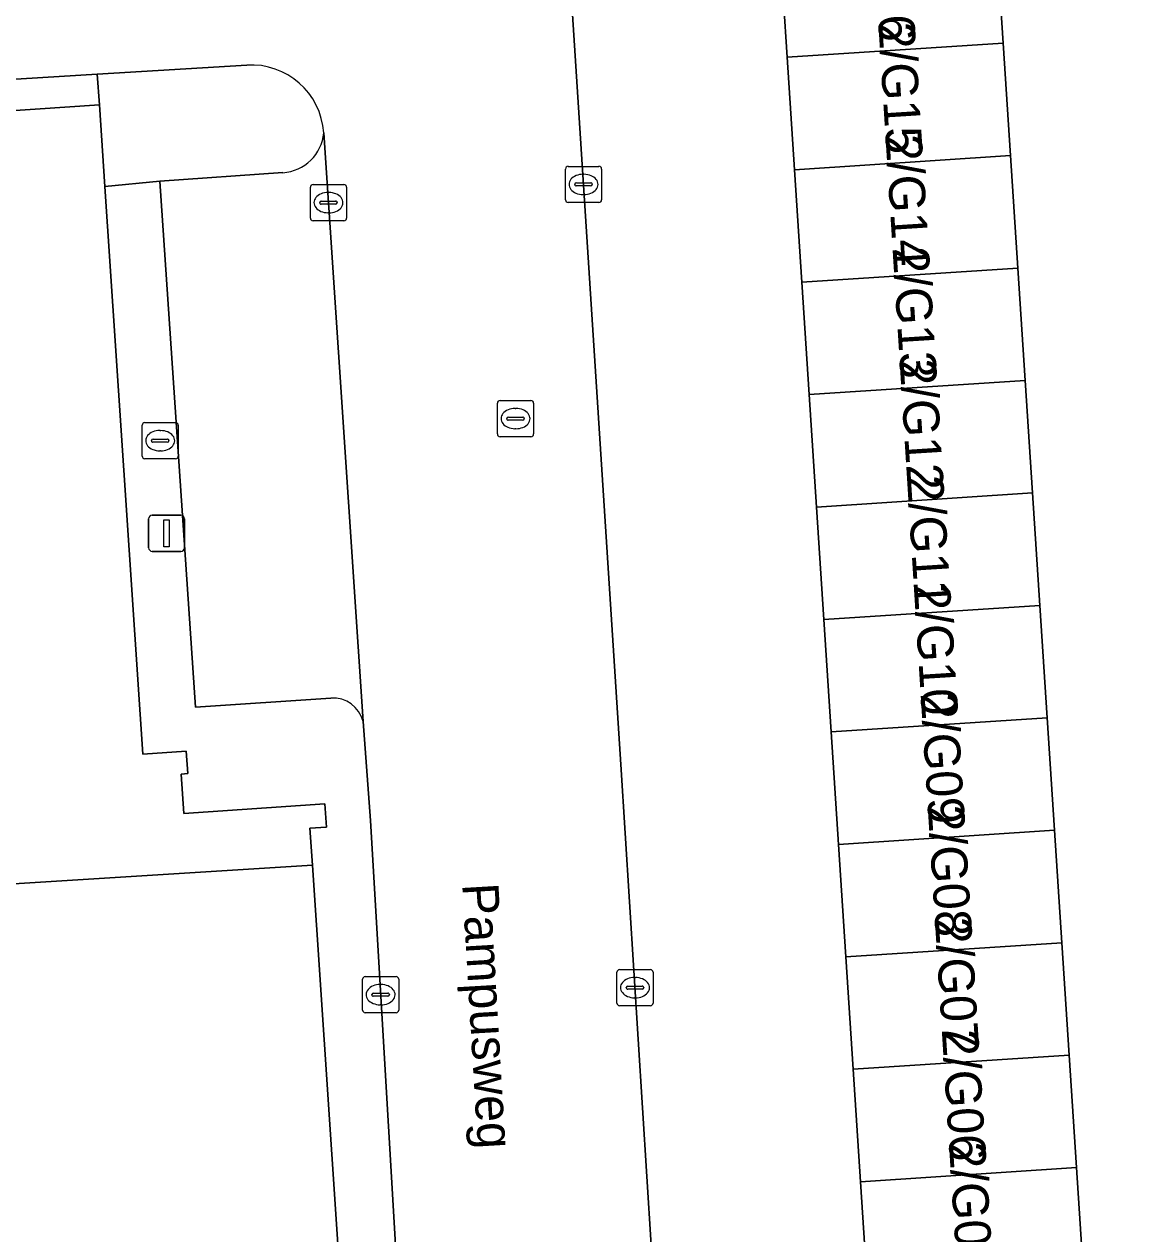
# Model space of a CAD drawing. Extents: x 159680 to 160786, y 387323 to 388340.
# Drawn here: x 160323.38 to 160353.93, y 387792.33 to 387825.78 of the extents above; entities that cross this region are included whole.
import ezdxf

# ---------------------------------------------------------------- set-up
doc = ezdxf.new("R2010")
doc.units = 0
for name, color, linetype in [('IMGEO_Kolk', 7, 'Continuous'), ('IMGEO_Lichtmast', 7, 'Continuous'), ('IMGEO_Openbare_ruimte_label', 7, 'Continuous'), ('IMGEO_Pand', 7, 'Continuous'), ('IMGEO_Pand_nummerreeks', 7, 'Continuous'), ('IMGEO_Parkeervlak_open', 7, 'Continuous'), ('IMGEO_Rijbaan_lokaal_open', 7, 'Continuous'), ('IMGEO_Rioolput', 7, 'Continuous'), ('IMGEO_Voetpad_open', 7, 'Continuous')]:
    doc.layers.add(name, color=color, linetype=linetype)

msp = doc.modelspace()

# ---------------------------------------------------------------- linework, layer by layer
at = {"layer": 'IMGEO_Kolk'}
for p, q in [((160338.348, 387820.92), (160338.348, 387821.772)), ((160338.423, 387821.846), (160339.275, 387821.846)), ((160339.349, 387821.772), (160339.349, 387820.92)), ((160331.369, 387821.342), (160332.221, 387821.342)), ((160338.607, 387821.34), (160338.607, 387821.352)), ((160338.65, 387821.389), (160339.048, 387821.389)), ((160338.836, 387821.626), (160338.861, 387821.626)), ((160339.091, 387821.352), (160339.091, 387821.34)), ((160331.294, 387820.416), (160331.294, 387821.268)), ((160331.782, 387821.122), (160331.807, 387821.122)), ((160332.295, 387821.268), (160332.295, 387820.416)), ((160339.045, 387821.303), (160338.647, 387821.303)), ((160338.859, 387821.066), (160338.834, 387821.066)), ((160331.553, 387820.836), (160331.553, 387820.848)), ((160331.991, 387820.799), (160331.593, 387820.799)), ((160331.596, 387820.885), (160331.994, 387820.885)), ((160332.037, 387820.848), (160332.037, 387820.836)), ((160339.275, 387820.846), (160338.423, 387820.846)), ((160332.221, 387820.342), (160331.369, 387820.342)), ((160331.805, 387820.562), (160331.78, 387820.562)), ((160339.846, 387799.639), (160340.698, 387799.639)), ((160332.736, 387798.519), (160332.736, 387799.371)), ((160332.811, 387799.445), (160333.663, 387799.445)), ((160333.737, 387799.371), (160333.737, 387798.519)), ((160339.771, 387798.713), (160339.771, 387799.565)), ((160340.259, 387799.419), (160340.284, 387799.419)), ((160340.772, 387799.565), (160340.772, 387798.713)), ((160332.995, 387798.939), (160332.995, 387798.951)), ((160333.433, 387798.902), (160333.035, 387798.902)), ((160333.038, 387798.988), (160333.436, 387798.988)), ((160333.224, 387799.225), (160333.249, 387799.225)), ((160333.479, 387798.951), (160333.479, 387798.939)), ((160340.03, 387799.133), (160340.03, 387799.145)), ((160340.468, 387799.096), (160340.07, 387799.096)), ((160340.073, 387799.182), (160340.471, 387799.182)), ((160340.514, 387799.145), (160340.514, 387799.133)), ((160333.247, 387798.665), (160333.222, 387798.665)), ((160340.698, 387798.639), (160339.846, 387798.639)), ((160340.282, 387798.859), (160340.257, 387798.859)), ((160333.663, 387798.445), (160332.811, 387798.445))]:
    msp.add_line(p, q, dxfattribs=at)
for points in [[(160338.348, 387820.92), (160338.348, 387821.772)], [(160338.423, 387821.846), (160339.275, 387821.846)], [(160339.349, 387821.772), (160339.349, 387820.92)], [(160331.369, 387821.342), (160332.221, 387821.342)], [(160331.294, 387820.416), (160331.294, 387821.268)], [(160332.295, 387821.268), (160332.295, 387820.416)], [(160339.275, 387820.846), (160338.423, 387820.846)], [(160332.221, 387820.342), (160331.369, 387820.342)], [(160339.846, 387799.639), (160340.698, 387799.639)], [(160332.736, 387798.519), (160332.736, 387799.371)], [(160332.811, 387799.445), (160333.663, 387799.445)], [(160333.737, 387799.371), (160333.737, 387798.519)], [(160339.771, 387798.713), (160339.771, 387799.565)], [(160340.772, 387799.565), (160340.772, 387798.713)], [(160340.698, 387798.639), (160339.846, 387798.639)], [(160333.663, 387798.445), (160332.811, 387798.445)]]:
    msp.add_lwpolyline(points, dxfattribs=at)
for centre, radius, start, end in [((160338.425, 387821.77), 0.0765, 91.552, 178.448), ((160338.425, 387821.77), 0.0765, 91.552, 178.448), ((160339.273, 387821.77), 0.0765, 1.552, 88.448), ((160339.273, 387821.77), 0.0765, 1.552, 88.448), ((160331.371, 387821.266), 0.0765, 91.552, 178.448), ((160331.371, 387821.266), 0.0765, 91.552, 178.448), ((160332.219, 387821.266), 0.0765, 1.552, 88.448), ((160332.219, 387821.266), 0.0765, 1.552, 88.448), ((160338.647, 387821.349), 0.0403, 85.8775, 175.7526), ((160338.644, 387821.339), 0.0366, 178.938, 274.7102), ((160339.048, 387821.346), 0.043, 264.8664, 352.4533), ((160339.052, 387821.351), 0.0386, 1.7309, 96.639), ((160331.593, 387820.845), 0.0403, 85.8775, 175.7526), ((160331.59, 387820.835), 0.0366, 178.938, 274.7102), ((160331.994, 387820.842), 0.043, 264.8664, 352.4533), ((160331.998, 387820.847), 0.0386, 1.7309, 96.639), ((160338.425, 387820.922), 0.0765, 181.552, 268.448), ((160338.425, 387820.922), 0.0765, 181.552, 268.448), ((160339.273, 387820.922), 0.0765, 271.552, 358.448), ((160339.273, 387820.922), 0.0765, 271.552, 358.448), ((160331.371, 387820.418), 0.0765, 181.552, 268.448), ((160331.371, 387820.418), 0.0765, 181.552, 268.448), ((160332.219, 387820.418), 0.0765, 271.552, 358.448), ((160332.219, 387820.418), 0.0765, 271.552, 358.448), ((160339.848, 387799.563), 0.0765, 91.552, 178.448), ((160339.848, 387799.563), 0.0765, 91.552, 178.448), ((160340.696, 387799.563), 0.0765, 1.552, 88.448), ((160340.696, 387799.563), 0.0765, 1.552, 88.448), ((160332.813, 387799.369), 0.0765, 91.552, 178.448), ((160332.813, 387799.369), 0.0765, 91.552, 178.448), ((160333.661, 387799.369), 0.0765, 1.552, 88.448), ((160333.661, 387799.369), 0.0765, 1.552, 88.448), ((160333.035, 387798.948), 0.0403, 85.8775, 175.7526), ((160333.032, 387798.938), 0.0366, 178.938, 274.7102), ((160333.436, 387798.945), 0.043, 264.8664, 352.4533), ((160333.44, 387798.95), 0.0386, 1.7309, 96.639), ((160340.07, 387799.142), 0.0403, 85.8775, 175.7526), ((160340.067, 387799.132), 0.0366, 178.938, 274.7102), ((160340.471, 387799.139), 0.043, 264.8664, 352.4533), ((160340.475, 387799.144), 0.0386, 1.7309, 96.639), ((160339.848, 387798.715), 0.0765, 181.552, 268.448), ((160339.848, 387798.715), 0.0765, 181.552, 268.448), ((160340.696, 387798.715), 0.0765, 271.552, 358.448), ((160340.696, 387798.715), 0.0765, 271.552, 358.448), ((160332.813, 387798.521), 0.0765, 181.552, 268.448), ((160332.813, 387798.521), 0.0765, 181.552, 268.448), ((160333.661, 387798.521), 0.0765, 271.552, 358.448), ((160333.661, 387798.521), 0.0765, 271.552, 358.448)]:
    msp.add_arc(centre, radius, start, end, dxfattribs=at)
for centre, major_axis, ratio, start_param, end_param in [((160338.835, 387821.346), (-0.387, 0.002), 0.722429, 4.712389, 7.853982), ((160338.86, 387821.346), (-0.39, 0.002), 0.717154, 1.570796, 4.712389), ((160331.781, 387820.842), (-0.387, 0.002), 0.722429, 4.712389, 7.853982), ((160331.806, 387820.842), (-0.39, 0.002), 0.717154, 1.570796, 4.712389), ((160340.258, 387799.139), (-0.387, 0.002), 0.722429, 4.712389, 7.853982), ((160340.283, 387799.139), (-0.39, 0.002), 0.717154, 1.570796, 4.712389), ((160333.223, 387798.945), (-0.387, 0.002), 0.722429, 4.712389, 7.853982), ((160333.248, 387798.945), (-0.39, 0.002), 0.717154, 1.570796, 4.712389)]:
    msp.add_ellipse(centre, major_axis=major_axis, ratio=ratio, start_param=start_param, end_param=end_param, dxfattribs=at)
at = {"layer": 'IMGEO_Lichtmast'}
for p, q in [((160326.822, 387811.302), (160326.822, 387812.102)), ((160326.822, 387812.102), (160326.822, 387811.302)), ((160326.922, 387812.202), (160327.712, 387812.202)), ((160327.712, 387812.202), (160326.922, 387812.202)), ((160327.812, 387812.102), (160327.812, 387811.302)), ((160327.812, 387811.302), (160327.812, 387812.102)), ((160327.712, 387811.202), (160326.922, 387811.202)), ((160326.922, 387811.202), (160327.712, 387811.202))]:
    msp.add_line(p, q, dxfattribs=at)
msp.add_lwpolyline([(160327.242, 387812.077), (160327.392, 387812.077), (160327.392, 387811.327), (160327.242, 387811.327), (160327.242, 387812.077)], dxfattribs=at)
for centre, start, end in [((160326.922, 387812.102), 90, 180), ((160326.922, 387812.102), 90, 180), ((160327.712, 387812.102), 0, 90), ((160327.712, 387812.102), 360, 90), ((160326.922, 387811.302), 180, 270), ((160326.922, 387811.302), 180, 270), ((160327.712, 387811.302), 270, 0), ((160327.712, 387811.302), 270, 0)]:
    msp.add_arc(centre, 0.1, start, end, dxfattribs=at)
at = {"layer": 'IMGEO_Pand'}
for points in [[(160344.482, 387824.862), (160350.454, 387825.251), (160350.251, 387828.36), (160344.279, 387827.97)], [(160344.684, 387821.753), (160350.656, 387822.142), (160350.454, 387825.251), (160344.482, 387824.862)], [(160325.609, 387821.289), (160325.458, 387823.545), (160312.863, 387822.702), (160314.285, 387801.439), (160319.097, 387801.761), (160331.352, 387802.523), (160331.283, 387803.548), (160331.738, 387803.578), (160331.695, 387804.219), (160327.791, 387803.958), (160327.719, 387805.043), (160327.902, 387805.056), (160327.861, 387805.674), (160326.659, 387805.594)], [(160344.887, 387818.644), (160350.859, 387819.034), (160350.656, 387822.142), (160344.684, 387821.753)], [(160345.09, 387815.535), (160351.062, 387815.925), (160350.859, 387819.034), (160344.887, 387818.644)], [(160345.292, 387812.427), (160351.264, 387812.816), (160351.062, 387815.925), (160345.09, 387815.535)], [(160345.495, 387809.318), (160351.467, 387809.707), (160351.264, 387812.816), (160345.292, 387812.427)], [(160345.698, 387806.209), (160351.67, 387806.598), (160351.467, 387809.707), (160345.495, 387809.318)], [(160345.9, 387803.1), (160351.872, 387803.49), (160351.67, 387806.598), (160345.698, 387806.209)], [(160346.103, 387799.991), (160352.075, 387800.381), (160351.872, 387803.49), (160345.9, 387803.1)], [(160331.352, 387802.523), (160319.097, 387801.761), (160322.017, 387758.116), (160322.036, 387757.833), (160333.839, 387758.606), (160334.288, 387758.635), (160334.155, 387760.62)], [(160346.306, 387796.883), (160352.278, 387797.272), (160352.075, 387800.381), (160346.103, 387799.991)], [(160346.509, 387793.774), (160352.481, 387794.163), (160352.278, 387797.272), (160346.306, 387796.883)], [(160346.711, 387790.665), (160352.683, 387791.054), (160352.481, 387794.163), (160346.509, 387793.774)]]:
    msp.add_lwpolyline(points, close=True, dxfattribs=at)
at = {"layer": 'IMGEO_Parkeervlak_open'}
for points in [[(160338.406, 387828.202), (160339.882, 387805.311), (160341.198, 387784.423), (160341.952, 387772.208)], [(160345.9, 387803.1), (160345.698, 387806.209), (160345.495, 387809.318), (160345.292, 387812.427), (160345.09, 387815.535), (160344.887, 387818.644), (160344.684, 387821.753), (160344.482, 387824.862), (160344.279, 387827.97), (160339.407, 387827.52)], [(160332.752, 387806.497), (160331.665, 387822.773)], [(160330.537, 387821.671), (160327.133, 387821.44), (160328.12, 387806.893), (160331.86, 387807.147)], [(160342.911, 387772.843), (160347.83, 387773.164), (160347.522, 387778.23), (160347.319, 387781.338), (160347.117, 387784.447), (160346.914, 387787.556), (160346.711, 387790.665), (160346.509, 387793.774), (160346.306, 387796.883), (160346.103, 387799.991), (160345.9, 387803.1)]]:
    msp.add_lwpolyline(points, dxfattribs=at)
for centre, radius, start, end in [((160330.455, 387822.883), 1.215, 273.863, 354.801), ((160331.918, 387806.289), 0.86, 13.9996, 93.8388)]:
    msp.add_arc(centre, radius, start, end, dxfattribs=at)
at = {"layer": 'IMGEO_Rijbaan_lokaal_open'}
for points in [[(160341.952, 387772.208), (160341.198, 387784.423), (160339.882, 387805.311), (160338.406, 387828.202), (160338.395, 387828.368)], [(160264.374, 387822.431), (160266.548, 387822.576), (160274.398, 387823.082), (160274.439, 387822.446), (160274.521, 387821.163), (160280.899, 387821.601), (160307.674, 387823.303), (160325.4, 387824.392), (160329.533, 387824.646)], [(160331.665, 387822.773), (160332.752, 387806.497), (160332.954, 387803.761), (160334.935, 387770.099)]]:
    msp.add_lwpolyline(points, dxfattribs=at)
msp.add_arc((160329.656, 387822.636), 2.013, 3.8934, 93.5068, dxfattribs=at)
at = {"layer": 'IMGEO_Rioolput'}
for p, q in [((160336.467, 387814.446), (160336.467, 387815.298)), ((160336.542, 387815.372), (160337.394, 387815.372)), ((160337.468, 387815.298), (160337.468, 387814.446)), ((160336.955, 387815.152), (160336.98, 387815.152)), ((160326.641, 387813.835), (160326.641, 387814.687)), ((160326.716, 387814.761), (160327.568, 387814.761)), ((160327.642, 387814.687), (160327.642, 387813.835)), ((160336.726, 387814.866), (160336.726, 387814.878)), ((160337.164, 387814.829), (160336.766, 387814.829)), ((160336.769, 387814.915), (160337.167, 387814.915)), ((160337.21, 387814.878), (160337.21, 387814.866)), ((160326.943, 387814.304), (160327.341, 387814.304)), ((160327.129, 387814.541), (160327.154, 387814.541)), ((160337.394, 387814.372), (160336.542, 387814.372)), ((160336.978, 387814.592), (160336.953, 387814.592)), ((160326.9, 387814.255), (160326.9, 387814.267)), ((160327.338, 387814.218), (160326.94, 387814.218)), ((160327.152, 387813.981), (160327.127, 387813.981)), ((160327.384, 387814.267), (160327.384, 387814.255)), ((160327.568, 387813.761), (160326.716, 387813.761))]:
    msp.add_line(p, q, dxfattribs=at)
for points in [[(160336.467, 387814.446), (160336.467, 387815.298)], [(160336.542, 387815.372), (160337.394, 387815.372)], [(160337.468, 387815.298), (160337.468, 387814.446)], [(160326.641, 387813.835), (160326.641, 387814.687)], [(160326.716, 387814.761), (160327.568, 387814.761)], [(160327.642, 387814.687), (160327.642, 387813.835)], [(160337.394, 387814.372), (160336.542, 387814.372)], [(160327.568, 387813.761), (160326.716, 387813.761)]]:
    msp.add_lwpolyline(points, dxfattribs=at)
for centre, radius, start, end in [((160336.544, 387815.296), 0.0765, 91.552, 178.448), ((160336.544, 387815.296), 0.0765, 91.552, 178.448), ((160337.392, 387815.296), 0.0765, 1.552, 88.448), ((160337.392, 387815.296), 0.0765, 1.552, 88.448), ((160326.718, 387814.685), 0.0765, 91.552, 178.448), ((160326.718, 387814.685), 0.0765, 91.552, 178.448), ((160327.566, 387814.685), 0.0765, 1.552, 88.448), ((160327.566, 387814.685), 0.0765, 1.552, 88.448), ((160336.766, 387814.875), 0.0403, 85.8775, 175.7526), ((160336.763, 387814.865), 0.0366, 178.938, 274.7102), ((160337.167, 387814.872), 0.043, 264.8664, 352.4533), ((160337.171, 387814.877), 0.0386, 1.7309, 96.639), ((160326.94, 387814.264), 0.0403, 85.8775, 175.7526), ((160327.345, 387814.266), 0.0386, 1.7309, 96.639), ((160336.544, 387814.448), 0.0765, 181.552, 268.448), ((160336.544, 387814.448), 0.0765, 181.552, 268.448), ((160337.392, 387814.448), 0.0765, 271.552, 358.448), ((160337.392, 387814.448), 0.0765, 271.552, 358.448), ((160326.937, 387814.254), 0.0366, 178.938, 274.7102), ((160327.341, 387814.261), 0.043, 264.8664, 352.4533), ((160326.718, 387813.837), 0.0765, 181.552, 268.448), ((160326.718, 387813.837), 0.0765, 181.552, 268.448), ((160327.566, 387813.837), 0.0765, 271.552, 358.448), ((160327.566, 387813.837), 0.0765, 271.552, 358.448)]:
    msp.add_arc(centre, radius, start, end, dxfattribs=at)
for centre, major_axis, ratio, start_param, end_param in [((160336.954, 387814.872), (-0.387, 0.002), 0.722429, 4.712389, 7.853982), ((160336.979, 387814.872), (-0.39, 0.002), 0.717154, 1.570796, 4.712389), ((160327.128, 387814.261), (-0.387, 0.002), 0.722429, 4.712389, 7.853982), ((160327.153, 387814.261), (-0.39, 0.002), 0.717154, 1.570796, 4.712389)]:
    msp.add_ellipse(centre, major_axis=major_axis, ratio=ratio, start_param=start_param, end_param=end_param, dxfattribs=at)
at = {"layer": 'IMGEO_Voetpad_open'}
for points in [[(160339.407, 387827.52), (160344.279, 387827.97), (160350.251, 387828.36), (160350.454, 387825.251), (160350.656, 387822.142), (160350.859, 387819.034), (160351.062, 387815.925), (160351.264, 387812.816), (160351.467, 387809.707), (160351.67, 387806.598), (160351.872, 387803.49), (160352.075, 387800.381), (160352.278, 387797.272), (160352.481, 387794.163), (160352.683, 387791.054), (160352.886, 387787.945), (160353.089, 387784.837), (160353.291, 387781.728), (160353.494, 387778.619), (160353.599, 387778.626), (160353.929, 387773.561), (160347.83, 387773.164), (160342.911, 387772.843)], [(160259.765, 387822.918), (160257.054, 387823.783), (160256.303, 387823.982), (160256, 387823.006), (160256.117, 387820.458), (160257.749, 387820.558), (160259.64, 387820.661), (160266.337, 387821.024), (160273.033, 387821.388), (160273.123, 387820.044), (160312.863, 387822.702), (160325.458, 387823.545), (160325.4, 387824.392), (160307.674, 387823.303), (160280.899, 387821.601), (160274.521, 387821.163), (160274.439, 387822.446)], [(160329.533, 387824.646), (160325.4, 387824.392), (160325.458, 387823.545), (160325.609, 387821.289), (160327.133, 387821.44), (160330.537, 387821.671)], [(160331.86, 387807.147), (160328.12, 387806.893), (160327.133, 387821.44), (160325.609, 387821.289), (160326.659, 387805.594), (160327.861, 387805.674), (160327.902, 387805.056), (160327.719, 387805.043), (160327.791, 387803.958), (160331.695, 387804.219), (160331.738, 387803.578), (160331.283, 387803.548), (160331.352, 387802.523), (160334.155, 387760.62), (160343.587, 387760.967)], [(160332.954, 387803.761), (160332.752, 387806.497)], [(160334.935, 387770.099), (160332.954, 387803.761)]]:
    msp.add_lwpolyline(points, dxfattribs=at)
for centre, radius, start, end in [((160329.656, 387822.636), 2.013, 3.8934, 93.5068), ((160330.455, 387822.883), 1.215, 273.863, 354.801), ((160331.918, 387806.289), 0.86, 13.9996, 93.8388)]:
    msp.add_arc(centre, radius, start, end, dxfattribs=at)

# ---------------------------------------------------------------- texts
at = {"layer": 'IMGEO_Openbare_ruimte_label'}
msp.add_text('Pampusweg', height=1, rotation=273.3833, dxfattribs=at).set_placement((160335.492, 387802.004))
at = {"layer": 'IMGEO_Pand_nummerreeks'}
for s, p in [('2/G16', (160346.805, 387828.905)), ('2/G15', (160347.001, 387825.8)), ('2/G14', (160347.197, 387822.696)), ('2/G13', (160347.393, 387819.591)), ('2/G12', (160347.588, 387816.493)), ('2/G11', (160347.791, 387813.272)), ('2/G10', (160347.98, 387810.274)), ('2/G09', (160348.17, 387807.267)), ('2/G08', (160348.366, 387804.156)), ('2/G07', (160348.562, 387801.054)), ('2/G06', (160348.757, 387797.95)), ('2/G05', (160348.953, 387794.845))]:
    msp.add_text(s, height=1, rotation=273.6085, dxfattribs=at).set_placement(p)

doc.saveas('drawing.dxf')
